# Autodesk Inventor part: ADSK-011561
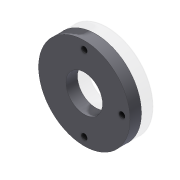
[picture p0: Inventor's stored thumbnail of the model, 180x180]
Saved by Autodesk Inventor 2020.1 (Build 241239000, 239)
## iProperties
Created: 2000-02
Part Number: ADSK-011561
Material: Pearson HRS
Document SubType Name: Modeling
Designer: sspink
Density: 7.83 g/cm^3
Appearance: Métal - Acier
Mass: 635.526 g
Surface Area: 192.674 cm^2
Volume: 81.1655 cm^3
Control State: 0
Checked Out: False
Master: False
Shininess: 0.0
Length Units: 11269
Angle Units: 11279
Time Units: 11290
Mass Units: 11283
Length Display Precision: 3
Angle Display Precision: 2
Compacted: True
Dimensions: 100x12,5x100 mm
Mass: 0,636 kg
VLT_Material: Pearson HRS
Density: 0.0
Volumn: 0.0
Area: 0.0
PropertySet Name: Model Information
Author: sspink
Revision Number: -
Title: ADSK-011561
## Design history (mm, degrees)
node "Solide1"
  node "Extrusion1" dims "d2" = 12.5, "d3" = 0
  node "Hole1" dims "d5" = 6.647, "d6" = 9.525, "d7" = 6.35, "d8" = 60 deg, "d9" = 22.2, "d10" = 118 deg, "d11" = 16
sketch "Sketch1"
  geometry: C1 r 50 at (0, 0); C2 r 20 at (0, 0); 1 further point
  constraints: 2 centre point, 2 coincident
  dimensions: "d0" = 100 diameter of C1; "d1" = 40 diameter of C2
sketch "Sketch2"
  geometry: L1 (0, 0)-(0, 41.25); L2 (0, 0)-(41.25, 0); L3 (0, 0)-(0, -41.25); C1 r 50 at (0, 0) reference; A1 r 41.25 centre (0, 0) between (0, 41.25) and (41.25, 0); 3 further points
  constraints: 6 end point, 4 coincident, 3 point on circle, 2 perpendicular, 1 centre point, 1 vertical
  dimensions: "d4" = 82.5 diameter of A1
node "Corps solides"
node "Corps surfaciques"
